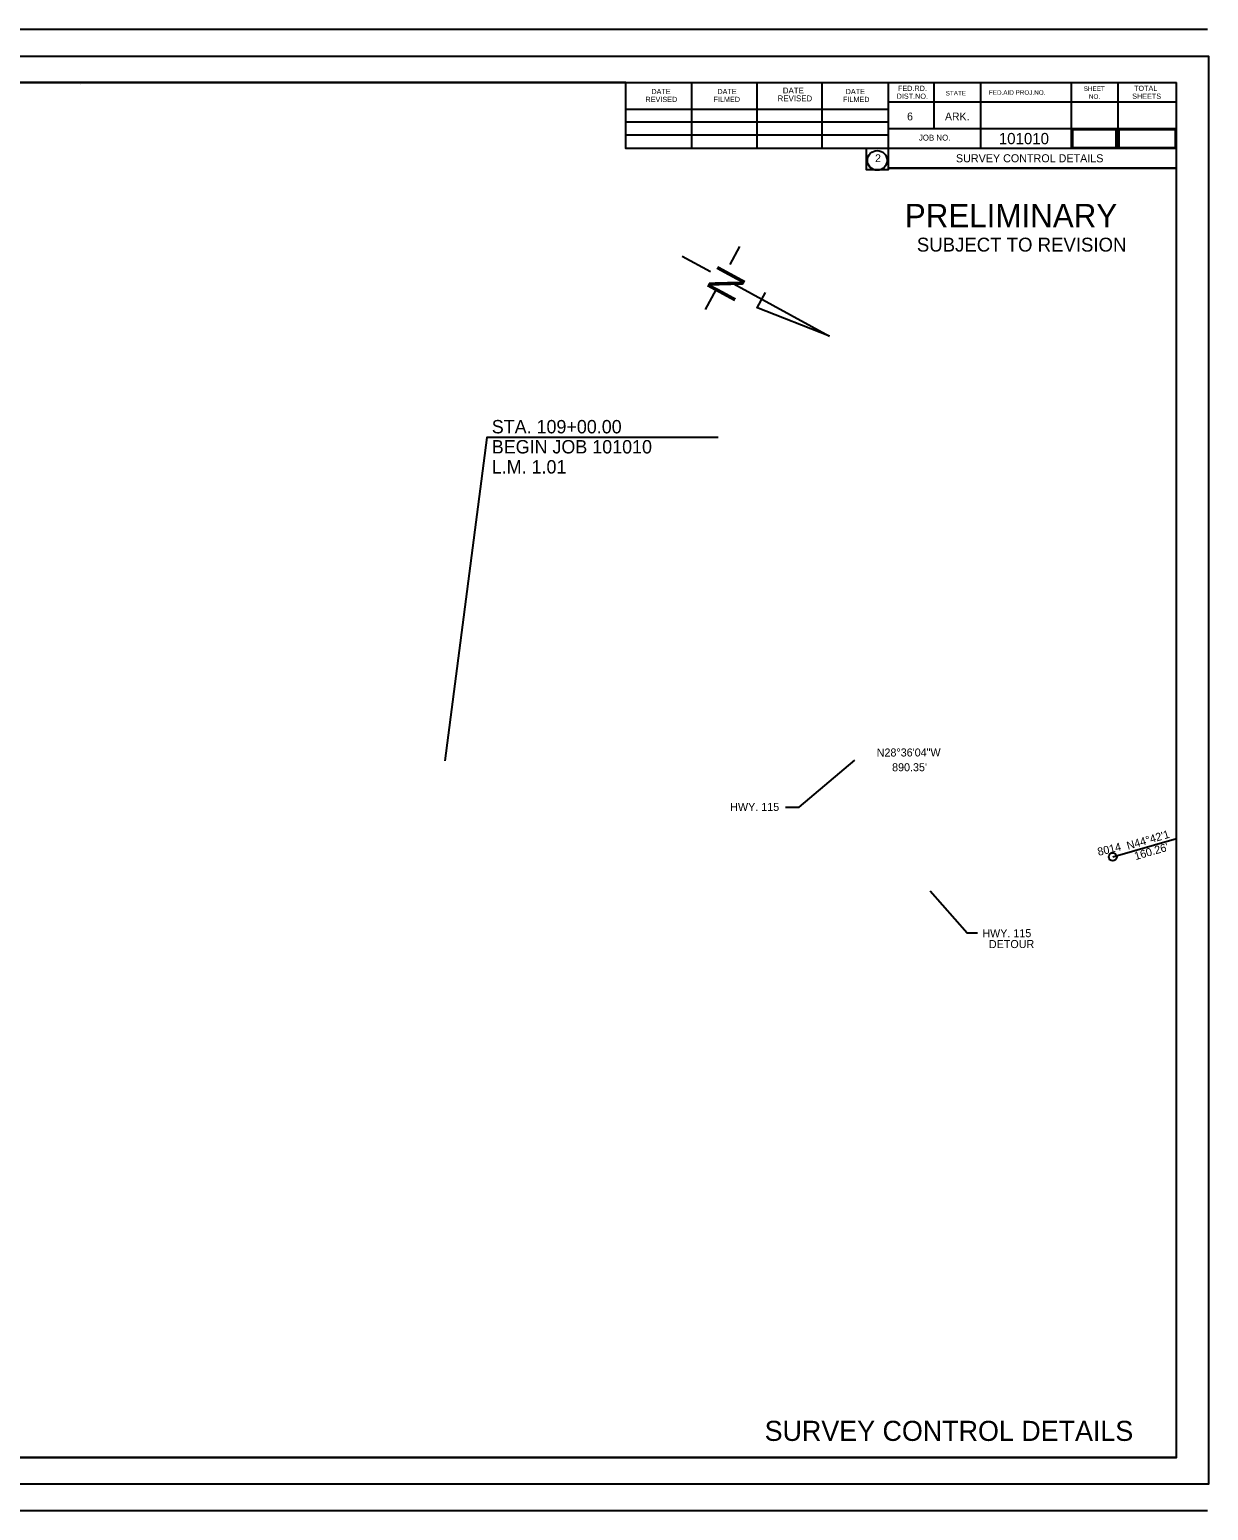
# Model space of a CAD drawing. Extents: x 3698 to 9589, y 10000 to 11106.
# Drawn here: x 6609 to 7490, y 10000 to 11106 of the extents above; entities that cross this region are included whole.
import ezdxf

# ---------------------------------------------------------------- set-up
doc = ezdxf.new("R2010")
doc.units = 0
for name, color, linetype in [('DATE', 7, 'Continuous'), ('GREEN_TXT', 7, 'Continuous'), ('R_Clearzone', 7, 'Continuous'), ('R_Culvert', 7, 'Continuous'), ('R_Detour', 7, 'Continuous'), ('R_Detour Annot', 7, 'Continuous'), ('R_Ditch', 7, 'Continuous'), ('R_Driveway Slope', 7, 'Continuous'), ('R_Proposed Const Limits', 7, 'Continuous'), ('R_Sub Surface', 7, 'Continuous'), ('R_Vert Alg LP', 7, 'Continuous'), ('RC Box Annot', 7, 'Continuous'), ('SEAL-INFO', 7, 'Continuous')]:
    doc.layers.add(name, color=color, linetype=linetype)

msp = doc.modelspace()

# ---------------------------------------------------------------- linework, layer by layer
for p, q in [((7139.3, 10944.1), (7132, 10930.6)), ((7096.6, 10936.9), (7117.7, 10925.5)), ((7121.7, 10911.6), (7113.8, 10897.1)), ((7135, 10916.1), (7206.5, 10877.2)), ((7158.4, 10909.7), (7152.2, 10898.4)), ((7206.5, 10877.2), (7151.9, 10898.6))]:
    msp.add_line(p, q)
at = {"layer": 'DATE'}
msp.add_lwpolyline([(5884.9, 11066.7), (5884.9, 10039.4), (7465.8, 10039.4), (7465.8, 11002.7), (7250.3, 11002.7), (7250.3, 11001.3), (7234.1, 11001.3), (7234.1, 11017.3), (7054.5, 11017.3), (7054.5, 11066.7)], close=True, dxfattribs=at)
msp.add_lwpolyline([(5884.9, 11066.7), (5884.9, 10039.4), (7465.8, 10039.4), (7465.8, 11002.7), (7250.3, 11002.7), (7250.3, 11001.3), (7234.1, 11001.3), (7234.1, 11017.3), (7054.5, 11017.3), (7054.5, 11066.7)], close=True, dxfattribs=at)
at = {"layer": 'GREEN_TXT'}
for p, q in [((7488.8, 11106.1), (5728.8, 11106.1)), ((5884.9, 11066.7), (7465.8, 11066.7)), ((6647.5, 11065.4), (6647.5, 11065.4)), ((6647.5, 11065.4), (6647.5, 11065.4)), ((7054.5, 11017.3), (7054.5, 11066.7)), ((7103.8, 11017.3), (7103.8, 11065.7)), ((7152.6, 11017.3), (7152.6, 11065.7)), ((7201, 11017.3), (7201, 11065.7)), ((7250.3, 11066.7), (7250.3, 11002.7)), ((7284.5, 11066.7), (7284.5, 11032)), ((7319.2, 11066.7), (7319.2, 11017.3)), ((7387.1, 11066.7), (7387.1, 11017.3)), ((7421.8, 11066.7), (7421.8, 11017.3)), ((7465.8, 10039.4), (7465.8, 11066.7)), ((7465.8, 11052), (7250.3, 11052)), ((7465.8, 11052.1), (7465.8, 11052.1)), ((7054.5, 11046.6), (7250.3, 11046.6)), ((7054.5, 11037.3), (7250.3, 11037.3)), ((7465.8, 11032), (7250.3, 11032)), ((7054.5, 11027.6), (7250.3, 11027.6)), ((7465.8, 11017.3), (7054.5, 11017.3)), ((7250.3, 11002.7), (7465.8, 11002.7)), ((7465.8, 10039.4), (5884.9, 10039.4)), ((5728.8, 10000), (7488.8, 10000))]:
    msp.add_line(p, q, dxfattribs=at)
msp.add_circle((7242.2, 11008.4), 7.33, dxfattribs=at)
at = {"layer": 'R_Clearzone'}
msp.add_lwpolyline([(5822.8, 11086.2), (7489.5, 11086.2), (7489.5, 10019.5), (5822.8, 10019.5)], close=True, dxfattribs=at)
at = {"layer": 'R_Culvert'}
msp.add_lwpolyline([(7173.6, 10525.4), (7183.9, 10525.4), (7225.4, 10560.3)], dxfattribs=at)
msp.add_circle((7418.1, 10488.1), 3, dxfattribs=at)
at = {"layer": 'R_Detour'}
msp.add_lwpolyline([(7123.3, 10801.4), (6950.7, 10801.4), (6919.3, 10559.8)], dxfattribs=at)
at = {"layer": 'R_Detour Annot'}
msp.add_lwpolyline([(7317.2, 10431.1), (7309.3, 10431.1), (7281.8, 10462.5)], dxfattribs=at)
at = {"layer": 'R_Ditch'}
msp.add_line((7418.1, 10488.1), (7465.8, 10502), dxfattribs=at)
at = {"layer": 'R_Driveway Slope'}
msp.add_lwpolyline([(7422.6, 11018), (7464.9, 11018), (7464.9, 11031.3), (7422.6, 11031.3)], close=True, dxfattribs=at)
at = {"layer": 'RC Box Annot'}
msp.add_lwpolyline([(7388.1, 11018), (7420.7, 11018), (7420.7, 11031.3), (7388.1, 11031.3)], close=True, dxfattribs=at)

# ---------------------------------------------------------------- texts
msp.add_text('N', height=23.3, rotation=241.4993).set_placement((7124.5, 10931.8))
at = {"layer": 'GREEN_TXT'}
for s, height, p in [('DATE', 3.91, (7073.5, 11057.9)), ('DATE', 3.91, (7122.8, 11057.9)), ('DATE', 4.4, (7171.7, 11058.4)), ('DATE', 3.91, (7218.6, 11057.9)), ('FED.RD.', 3.91, (7257.7, 11060.3)), ('SHEET', 3.42, (7396.4, 11060.3)), ('TOTAL', 3.91, (7434, 11060.3)), ('REVISED', 3.91, (7069.1, 11052)), ('FILMED', 3.91, (7119.9, 11052)), ('REVISED', 4.4, (7167.8, 11052.5)), ('FILMED', 3.91, (7216.6, 11052)), ('DIST.NO.', 3.91, (7256.7, 11054.4)), ('STATE', 3.42, (7293.3, 11056.9)), ('FED.AID PROJ.NO.', 3.42, (7325.6, 11057.4)), ('NO.', 3.42, (7400.3, 11054.4)), ('SHEETS', 3.91, (7432.6, 11054.4)), ('6', 5.86, (7264.5, 11038.3)), ('ARK.', 5.86, (7292.8, 11038.3)), ('JOB NO.', 4.4, (7273.3, 11023.2)), ('2', 5.86, (7240.6, 11007.1)), ('SURVEY CONTROL DETAILS', 15, (7158.1, 10051.9))]:
    msp.add_text(s, height=height, dxfattribs=at).set_placement(p)
at = {"layer": 'R_Culvert'}
for s, p in [('N28%%d36\'04"W', (7241.8, 10563.1)), ("890.35'", (7253.3, 10552.1)), ('HWY. 115', (7132.4, 10522.4)), ('HWY. 115', (7320.7, 10428.1)), ('DETOUR', (7325.6, 10420))]:
    msp.add_text(s, height=6, rotation=0.1002, dxfattribs=at).set_placement(p)
at = {"layer": 'R_Detour'}
for s, p in [('STA. 109+00.00', (6954.3, 10804.5)), ('BEGIN JOB 101010', (6954.3, 10789.5)), ('L.M. 1.01', (6954.3, 10774.5))]:
    msp.add_text(s, height=10, dxfattribs=at).set_placement(p)
at = {"layer": 'R_Proposed Const Limits'}
for s, p in [("N44%%d42'1", (7429.5, 10493.4)), ("160.26'", (7435.2, 10485.7))]:
    msp.add_text(s, height=6, rotation=16.2034, dxfattribs=at).set_placement(p)
at = {"layer": 'R_Sub Surface'}
msp.add_text('8014', height=6, rotation=13.5145, dxfattribs=at).set_placement((7407.5, 10488.9))
at = {"layer": 'R_Vert Alg LP'}
for s, height, p in [('101010', 8.4, (7333, 11020.5)), ('SURVEY CONTROL DETAILS', 6, (7301, 11007))]:
    msp.add_text(s, height=height, dxfattribs=at).set_placement(p)
at = {"layer": 'SEAL-INFO'}
for s, height, p in [('PRELIMINARY', 17.5, (7262.8, 10958.4)), ('SUBJECT TO REVISION', 10.376, (7271.8, 10940.3))]:
    msp.add_text(s, height=height, dxfattribs=at).set_placement(p)

doc.saveas('drawing.dxf')
